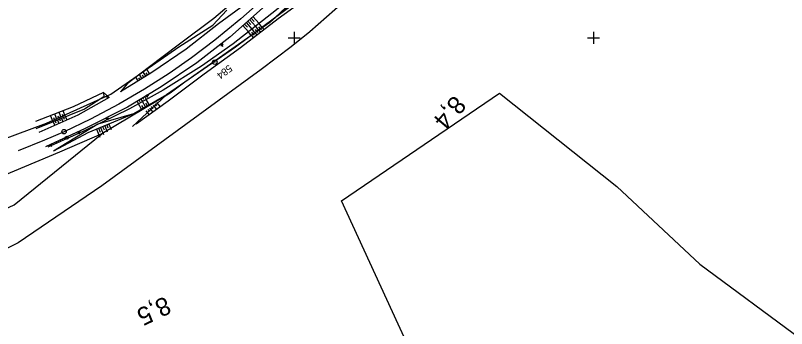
# Model space of a CAD drawing. Extents: x -779302 to -774398, y -1144902 to -1142831.
# Drawn here: x -778493.1 to -778235.6, y -1143997 to -1143892.5 of the extents above; entities that cross this region are included whole.
import ezdxf

# ---------------------------------------------------------------- set-up
doc = ezdxf.new("R2010")
doc.units = 0
for name, color, linetype in [('hektosit - Vrstva 5', 7, 'Continuous'), ('Hranice parcel', 7, 'Continuous'), ('zjednodus_g_situ-seda - Vrstva 1', 7, 'Continuous'), ('zjednodus_g_situ-seda - Vrstva 48', 7, 'Continuous'), ('zjednodus_g_situ-seda - Vrstva 49', 7, 'Continuous'), ('zjednodus_g_situ-seda - Vrstva 63', 7, 'Continuous'), ('zjednodus_g_situ-seda - Vrstva 7', 7, 'Continuous')]:
    doc.layers.add(name, color=color, linetype=linetype)

msp = doc.modelspace()

# ---------------------------------------------------------------- linework, layer by layer
at = {"layer": 'hektosit - Vrstva 5'}
for p, q in [((-778400, -1143898), (-778400, -1143902)), ((-778300, -1143898), (-778300, -1143902)), ((-778402, -1143900), (-778398, -1143900)), ((-778302, -1143900), (-778298, -1143900))]:
    msp.add_line(p, q, dxfattribs=at)
at = {"layer": 'Hranice parcel'}
for p, q in [((-778382.36, -1143870.73), (-778408.15, -1143894.88)), ((-778408.15, -1143894.88), (-778436.49, -1143914.8))]:
    msp.add_line(p, q, dxfattribs=at)
for points in [[(-778154.14, -1143725.63), (-778179.34, -1143737.13), (-778262.61, -1143772.29), (-778285.69, -1143783.2), (-778298.53, -1143795.65), (-778343.69, -1143848.48), (-778375.32, -1143880.74), (-778394.75, -1143898.05), (-778401.03, -1143902.99), (-778411.09, -1143910.58), (-778464.29, -1143949.38), (-778492.24, -1143968.43), (-778546.37, -1143995.76), (-778568.54, -1144004.65), (-778592.3, -1144003.98), (-778622.87, -1144002.93), (-778634.83, -1144006.49), (-778697.09, -1144033.84)], [(-778408.15, -1143894.88), (-778377.97, -1143868.11), (-778330.39, -1143816.43), (-778317.81, -1143801.23)], [(-778438.57, -1143903.04), (-778427.15, -1143895.83), (-778422.45, -1143890.8)], [(-778772.05, -1143948.3), (-778751.88, -1143945.64), (-778731.03, -1143944.98), (-778640.44, -1143948.79), (-778573.81, -1143948.98), (-778530.68, -1143943.56), (-778508.53, -1143938.08), (-778482.71, -1143928.49), (-778461.25, -1143918.78), (-778438.57, -1143903.04)], [(-778436.49, -1143914.8), (-778441.4, -1143918.51), (-778464.29, -1143932.05)], [(-778345.68, -1144038.15), (-778384.23, -1143954.42), (-778331.44, -1143918.51), (-778292.2, -1143949.58), (-778264.58, -1143975.57), (-778230.79, -1144000.49), (-778212.5, -1143990.19)], [(-778464.29, -1143932.05), (-778478.41, -1143938.21), (-778505.36, -1143949.37), (-778528.85, -1143955.36), (-778554.83, -1143958.91), (-778596.33, -1143959.85), (-778639.48, -1143961.79), (-778729.25, -1143967.31), (-778777.61, -1143966.72), (-778817, -1143978.34), (-778852.71, -1143996.58), (-778896.61, -1144013.46), (-778946.7, -1144032.01)], [(-778932.54, -1144104.86), (-778909.06, -1144098.66), (-778843.23, -1144080.83), (-778808.28, -1144071.82), (-778777.6, -1144061.48), (-778758.9, -1144052.04), (-778672.12, -1144008.6), (-778646.17, -1143998.44), (-778630.5, -1143993.45), (-778615.72, -1143992.45), (-778588.24, -1143994.2), (-778568.8, -1143990.98), (-778493.54, -1143955.7), (-778464.29, -1143932.05)]]:
    msp.add_lwpolyline(points, dxfattribs=at)
at = {"layer": 'zjednodus_g_situ-seda - Vrstva 1'}
msp.add_lwpolyline([(-778410.28, -1143886.83), (-778417.79, -1143893.62), (-778426.53, -1143900.82), (-778434.27, -1143906.66), (-778441.78, -1143911.85), (-778449.95, -1143917.08), (-778458.6, -1143922.12), (-778468.04, -1143927.12), (-778476.86, -1143931.34), (-778483.39, -1143934.2), (-778492.14, -1143937.7)], dxfattribs=at)
at = {"layer": 'zjednodus_g_situ-seda - Vrstva 48'}
for p, q in [((-778415.48, -1143894.4), (-778414.49, -1143895.51)), ((-778414.92, -1143893.91), (-778412.91, -1143896.16)), ((-778414.35, -1143893.41), (-778413.33, -1143894.55)), ((-778413.79, -1143892.91), (-778411.72, -1143895.24)), ((-778417.16, -1143895.9), (-778415.28, -1143898.01)), ((-778416.6, -1143895.4), (-778415.64, -1143896.47)), ((-778416.04, -1143894.9), (-778414.1, -1143897.09)), ((-778413.12, -1143898.29), (-778414.05, -1143897.05)), ((-778411.92, -1143897.39), (-778412.86, -1143896.13)), ((-778411.31, -1143896.95), (-778411.79, -1143896.31)), ((-778410.71, -1143896.5), (-778411.68, -1143895.21)), ((-778411.29, -1143896.93), (-778410.99, -1143897.34)), ((-778410.69, -1143896.48), (-778410.09, -1143897.29)), ((-778414.32, -1143899.19), (-778415.23, -1143897.97)), ((-778414.3, -1143899.17), (-778413.65, -1143900.04)), ((-778413.72, -1143898.74), (-778414.18, -1143898.12)), ((-778413.7, -1143898.72), (-778413.38, -1143899.15)), ((-778413.1, -1143898.27), (-778412.46, -1143899.12)), ((-778412.52, -1143897.84), (-778412.98, -1143897.21)), ((-778412.49, -1143897.83), (-778412.18, -1143898.25)), ((-778411.89, -1143897.38), (-778411.28, -1143898.21)), ((-778450.84, -1143913.6), (-778451.68, -1143912.24)), ((-778450.2, -1143913.2), (-778450.64, -1143912.5)), ((-778449.57, -1143912.81), (-778450.48, -1143911.34)), ((-778448.93, -1143912.41), (-778449.4, -1143911.65)), ((-778448.29, -1143912.02), (-778449.27, -1143910.44)), ((-778452.12, -1143914.39), (-778452.89, -1143913.14)), ((-778451.48, -1143914), (-778451.88, -1143913.34)), ((-778450.57, -1143920.06), (-778450.32, -1143920.49)), ((-778449.93, -1143919.67), (-778449.4, -1143920.55)), ((-778452.5, -1143921.23), (-778452.03, -1143922.01)), ((-778450.99, -1143923.8), (-778452.03, -1143922.01)), ((-778451.86, -1143920.84), (-778451.61, -1143921.24)), ((-778451.21, -1143920.45), (-778450.71, -1143921.28)), ((-778450.34, -1143923.42), (-778450.86, -1143922.53)), ((-778449.69, -1143923.05), (-778450.72, -1143921.28)), ((-778449.04, -1143922.67), (-778449.55, -1143921.79)), ((-778448.4, -1143922.29), (-778449.41, -1143920.55)), ((-778447.14, -1143922.49), (-778446.03, -1143923.91)), ((-778446.55, -1143922.02), (-778445.98, -1143922.75)), ((-778445.96, -1143921.56), (-778444.81, -1143923.03)), ((-778479.12, -1143927.45), (-778479.95, -1143925.4)), ((-778477.73, -1143926.89), (-778478.55, -1143924.85)), ((-778476.34, -1143926.33), (-778477.15, -1143924.31)), ((-778449.5, -1143924.34), (-778448.46, -1143925.67)), ((-778448.91, -1143923.88), (-778448.38, -1143924.55)), ((-778448.32, -1143923.42), (-778447.24, -1143924.79)), ((-778447.73, -1143922.95), (-778447.18, -1143923.65)), ((-778480.51, -1143928.02), (-778481.35, -1143925.94)), ((-778480.5, -1143928.01), (-778480, -1143929.25)), ((-778479.81, -1143927.73), (-778480.23, -1143926.7)), ((-778479.81, -1143927.73), (-778479.56, -1143928.34)), ((-778479.11, -1143927.45), (-778478.63, -1143928.64)), ((-778478.42, -1143927.17), (-778478.84, -1143926.15)), ((-778478.42, -1143927.17), (-778478.18, -1143927.75)), ((-778477.72, -1143926.89), (-778477.26, -1143928.02)), ((-778477.03, -1143926.61), (-778477.44, -1143925.59)), ((-778477.03, -1143926.61), (-778476.8, -1143927.16)), ((-778476.33, -1143926.32), (-778475.89, -1143927.41)), ((-778466.07, -1143930.48), (-778464.95, -1143933.17)), ((-778465.37, -1143930.19), (-778464.85, -1143931.46)), ((-778464.68, -1143929.91), (-778463.69, -1143932.29)), ((-778463.98, -1143929.62), (-778463.52, -1143930.74)), ((-778463.29, -1143929.33), (-778462.43, -1143931.42)), ((-778462.6, -1143929.05), (-778462.2, -1143930.02)), ((-778461.91, -1143928.76), (-778461.17, -1143930.55)), ((-778479.54, -1143934.81), (-778479.36, -1143935.19)), ((-778478.86, -1143934.49), (-778478.77, -1143934.69)), ((-778478.18, -1143934.18), (-778477.99, -1143934.58)), ((-778477.5, -1143933.86), (-778477.4, -1143934.07)), ((-778476.82, -1143933.54), (-778476.62, -1143933.98))]:
    msp.add_line(p, q, dxfattribs=at)
at = {"layer": 'zjednodus_g_situ-seda - Vrstva 49'}
for p, q in [((-778461.75, -1143919.93), (-778463.73, -1143918.3)), ((-778463.73, -1143918.3), (-778463.63, -1143919.74)), ((-778461.75, -1143919.93), (-778463.63, -1143919.74)), ((-778442.67, -1143918.97), (-778454.04, -1143929.6))]:
    msp.add_line(p, q, dxfattribs=at)
for points in [[(-778333.99, -1143787.58), (-778336.61, -1143791.37), (-778344.02, -1143801.11), (-778354.3, -1143816.64), (-778366.78, -1143832.56), (-778374.67, -1143843.15), (-778383.24, -1143853.65), (-778392.93, -1143865.25), (-778400.17, -1143872.91), (-778405.12, -1143878.31), (-778413.66, -1143886.77), (-778425.31, -1143895.33), (-778436.1, -1143903.82), (-778447.56, -1143911.56), (-778458.03, -1143918.06)], [(-778340.87, -1143806.86), (-778350.26, -1143819.94), (-778362.8, -1143835.59), (-778371.26, -1143846.04), (-778379.57, -1143856.84), (-778389.52, -1143868.23), (-778396.63, -1143876.32), (-778401.71, -1143881.72), (-778410.59, -1143890.06), (-778421.51, -1143899.76), (-778432.57, -1143908.39), (-778444.41, -1143916.32), (-778455.64, -1143923.14), (-778469.84, -1143930.28), (-778483.01, -1143936.43)], [(-778410.15, -1143877.82), (-778418.05, -1143886.01), (-778426.84, -1143893.59), (-778438.27, -1143902.12), (-778448.73, -1143910.03), (-778455.82, -1143915.33), (-778458.03, -1143918.06)], [(-778400.33, -1143886.13), (-778407.42, -1143891.9), (-778420.44, -1143902.01), (-778430.94, -1143909.45), (-778443.81, -1143917.42), (-778454.99, -1143923.66), (-778469.59, -1143930.87), (-778482.28, -1143936.48)], [(-778398.28, -1143887.17), (-778406.57, -1143893.41), (-778419.61, -1143903.13), (-778430.36, -1143910.57), (-778442.67, -1143918.97), (-778453.67, -1143925.36), (-778468.92, -1143931.66), (-778480.34, -1143937.81)], [(-778396.1, -1143886.88), (-778405.32, -1143893.61), (-778417.98, -1143903.37), (-778430.05, -1143912.09), (-778442.15, -1143921.1), (-778452.75, -1143928.77)], [(-778463.73, -1143918.3), (-778473.78, -1143922.99), (-778486.36, -1143927.9)], [(-778463.63, -1143919.74), (-778470.01, -1143923.77), (-778486.29, -1143930.36)], [(-778461.75, -1143919.93), (-778472.21, -1143925.76), (-778485.24, -1143931.6)], [(-778453.67, -1143925.36), (-778465.6, -1143928.8), (-778480.34, -1143937.81)]]:
    msp.add_lwpolyline(points, dxfattribs=at)
at = {"layer": 'zjednodus_g_situ-seda - Vrstva 63'}
msp.add_line((-778426.55, -1143908.1), (-778426.45, -1143908.1), dxfattribs=at)
msp.add_circle((-778426.5, -1143908.1), 0.756, dxfattribs=at)
at = {"layer": 'zjednodus_g_situ-seda - Vrstva 7'}
for p, q in [((-778423.69, -1143902.15), (-778424.48, -1143902.76)), ((-778423.78, -1143902.85), (-778424.39, -1143902.06)), ((-778448.71, -1143919.22), (-778449.56, -1143919.73)), ((-778448.88, -1143919.9), (-778449.39, -1143919.04)), ((-778462, -1143926.8), (-778462.88, -1143927.27)), ((-778462.21, -1143927.48), (-778462.67, -1143926.59)), ((-778471.43, -1143931.53), (-778472.34, -1143931.95)), ((-778471.68, -1143932.19), (-778472.09, -1143931.28)), ((-778480.72, -1143935.73), (-778481.63, -1143936.14)), ((-778480.97, -1143936.39), (-778481.38, -1143935.48)), ((-778475.91, -1143933.32), (-778476, -1143933.36))]:
    msp.add_line(p, q, dxfattribs=at)
for centre, radius in [((-778476.86, -1143931.34), 0.75), ((-778475.96, -1143933.34), 0.5)]:
    msp.add_circle(centre, radius, dxfattribs=at)

# ---------------------------------------------------------------- texts
at = {"layer": 'zjednodus_g_situ-seda - Vrstva 63'}
msp.add_text('584', height=2.4, rotation=217.014, dxfattribs=at).set_placement((-778421.82, -1143908.82))
at = {"layer": 'zjednodus_g_situ-seda - Vrstva 7'}
for s, rotation, p in [('8,4', 229.5104, (-778346.66, -1143918.85)), ('8,5', 205.5986, (-778443.07, -1143986.1))]:
    msp.add_text(s, height=6, rotation=rotation, dxfattribs=at).set_placement(p)

doc.saveas('drawing.dxf')
